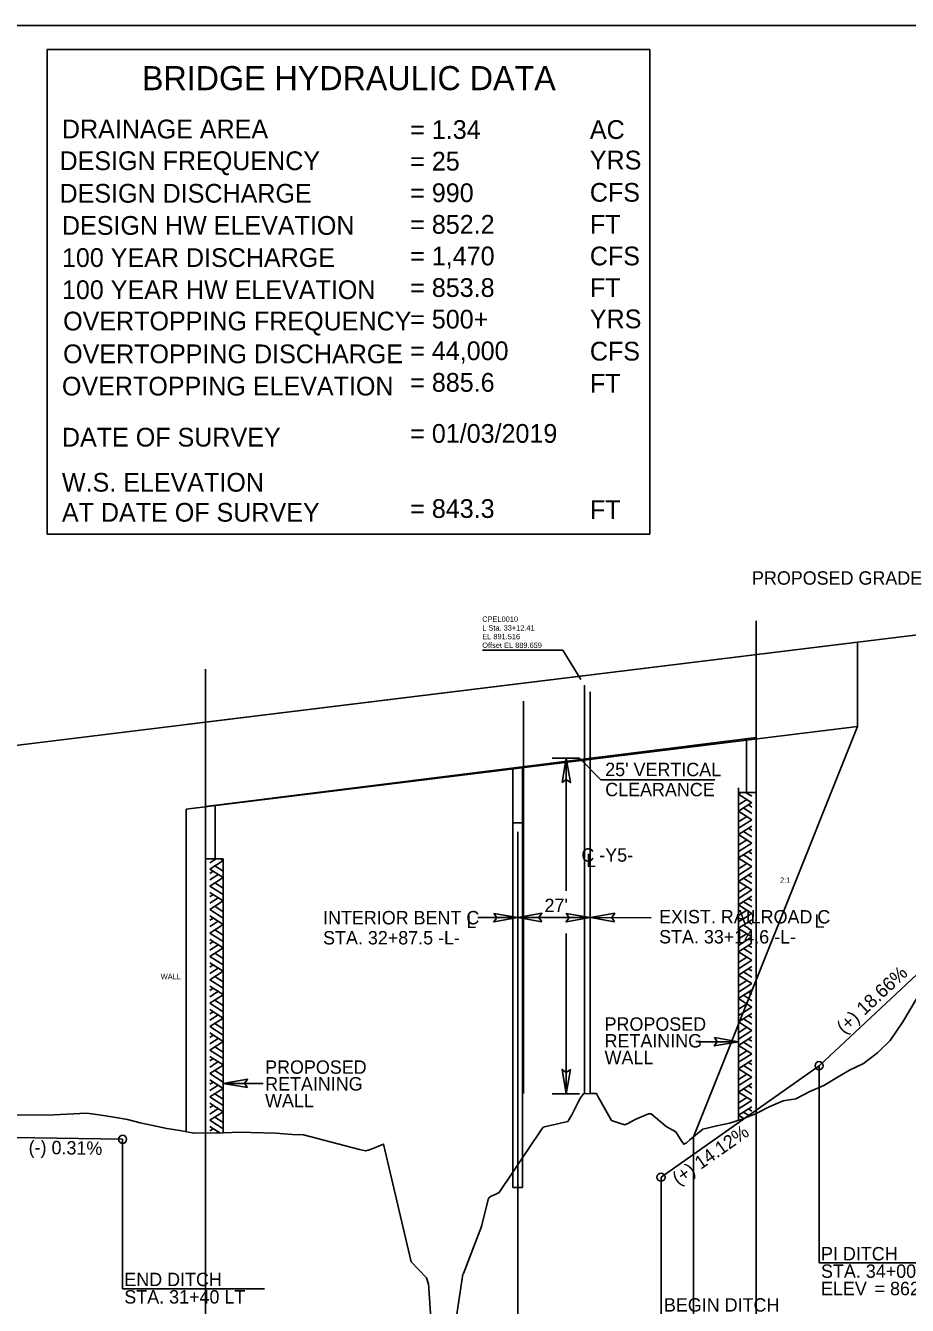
# Model space of a CAD drawing. Extents: x 1968019 to 1983409, y 545058 to 567558.
# Drawn here: x 1970946.7 to 1971275.9, y 566530.6 to 567008.4 of the extents above; entities that cross this region are included whole.
import ezdxf

# ---------------------------------------------------------------- set-up
doc = ezdxf.new("R2010")
doc.units = 0
for name, color, linetype in [('Exist Vertical Profile Ground Line', 7, 'Continuous'), ('Old_Level_20', 7, 'Continuous'), ('Prop Grid Mask', 7, 'Continuous'), ('Prop Plan Preparation Sheet Bridge Report Limited Study CELL', 7, 'Continuous'), ('Prop Roadway Bridge', 7, 'Continuous'), ('Prop Terminator CELL', 7, 'Continuous'), ('Prop Vertical Profile Ditch Grade Left', 7, 'Continuous'), ('Prop Vertical Profile Ditch Grade Left Label', 7, 'Continuous'), ('Prop Vertical Profile Grade', 7, 'Continuous'), ('Scratch_Level_1', 7, 'Continuous'), ('Scratch_Level_8', 7, 'Continuous'), ('Sheet Data Text CELL', 7, 'Continuous')]:
    doc.layers.add(name, color=color, linetype=linetype)

msp = doc.modelspace()

# ---------------------------------------------------------------- linework, layer by layer
at = {"layer": 'Exist Vertical Profile Ground Line'}
for points in [[(1971274.29, 566636.39), (1971279.33, 566645.04)], [(1971106.99, 566522.3), (1971109.93, 566542.19), (1971110.22, 566542.43), (1971116.96, 566559.99), (1971119.55, 566570.6), (1971120.52, 566571.34), (1971122.07, 566572.02), (1971123.55, 566572.68), (1971139.36, 566596.24), (1971140, 566597.16), (1971140.41, 566597.29), (1971149.23, 566599.25), (1971150.69, 566601.68), (1971153.07, 566606.51), (1971153.96, 566608.07), (1971154.97, 566609.62), (1971157.85, 566609.64), (1971159.91, 566609.65), (1971160.65, 566608.17), (1971161.6, 566606.49), (1971164.47, 566601.39), (1971165.48, 566599.66), (1971168.51, 566598.6), (1971170.44, 566598), (1971171.86, 566598.62), (1971174.29, 566599.95), (1971179.26, 566602.04), (1971180.33, 566602.12), (1971185.94, 566597.41), (1971189.54, 566595.36), (1971191.73, 566591.77), (1971192.28, 566591.09), (1971192.43, 566590.95), (1971192.45, 566590.71), (1971193.49, 566591.26), (1971194.72, 566592.36), (1971199.54, 566596.34), (1971204.8, 566597.64), (1971209.54, 566598.58), (1971214.29, 566600.07), (1971219.54, 566602.16), (1971224.29, 566604.77), (1971229.54, 566606.89), (1971234.29, 566607.73), (1971239.54, 566610.4), (1971244.8, 566612.64), (1971249.54, 566615.59), (1971254.29, 566618.36), (1971259.54, 566620.9), (1971264.8, 566624.91), (1971269.55, 566629.52), (1971274.29, 566636.39)], [(1970915.49, 566601.57), (1970957.3, 566601.67), (1970969.53, 566602.4), (1970974.27, 566601.74), (1970980.4, 566600.76), (1970984.79, 566599.95), (1970989.53, 566598.79), (1970994.28, 566597.71), (1970999.53, 566596.67), (1971004.28, 566595.84), (1971009.53, 566594.85), (1971020.55, 566595.01), (1971026.87, 566595.2), (1971030.89, 566595.08), (1971040.13, 566594.85), (1971046.38, 566594.41), (1971050.52, 566594.2), (1971071.37, 566588.81), (1971073.6, 566588.27), (1971074.15, 566588.41), (1971075.54, 566588.75), (1971080.41, 566590.8), (1971090.65, 566546.83), (1971096.42, 566540.87), (1971097.14, 566538.44), (1971097.26, 566537.05), (1971098.21, 566523.79)]]:
    msp.add_lwpolyline(points, dxfattribs=at)
at = {"layer": 'Prop Grid Mask'}
msp.add_lwpolyline([(1970954.74, 566999.5), (1971179.74, 566999.5), (1971179.74, 566818.58), (1970954.74, 566818.58)], close=True, dxfattribs=at)
at = {"layer": 'Prop Plan Preparation Sheet Bridge Report Limited Study CELL'}
for p, q in [((1971153.55, 566734.84), (1971143.38, 566734.84)), ((1971148.61, 566685.35), (1971148.61, 566734.84)), ((1971153.55, 566734.84), (1971161.5, 566726.82)), ((1971161.5, 566726.82), (1971204.04, 566726.82)), ((1971157.57, 566692.23), (1971157.57, 566609.63)), ((1971130.56, 566675.37), (1971115.61, 566675.37)), ((1971157.57, 566675.37), (1971130.46, 566675.37)), ((1971180.28, 566675.34), (1971157.67, 566675.4)), ((1971148.61, 566609.62), (1971148.61, 566669.37)), ((1971197.93, 566629.03), (1971212.87, 566629.03)), ((1971035.48, 566613.42), (1971020.54, 566613.42)), ((1971153.55, 566609.62), (1971143.38, 566609.62))]:
    msp.add_line(p, q, dxfattribs=at)
at = {"layer": 'Prop Roadway Bridge'}
for p, q in [((1971219.46, 566773.52), (1971219.46, 566742.57)), ((1971013.96, 566748.31), (1971013.96, 566716.88)), ((1971013.96, 566716.88), (1971219.46, 566742.57)), ((1971215.87, 566722.13), (1971215.87, 566742.13)), ((1971219.46, 566742.57), (1971219.46, 566722.13)), ((1971128.66, 566730.99), (1971128.66, 566710.73)), ((1971132.25, 566731.43), (1971132.25, 566710.73)), ((1971212.87, 566723.83), (1971212.87, 566631.65)), ((1971215.87, 566722.13), (1971212.87, 566722.13)), ((1971212.87, 566722.13), (1971212.87, 566599.63)), ((1971212.87, 566721.47), (1971213.9, 566722.13)), ((1971212.87, 566721.47), (1971217.87, 566718.28)), ((1971212.87, 566717.47), (1971216.01, 566719.47)), ((1971212.87, 566715.1), (1971217.87, 566718.29)), ((1971215.56, 566722.13), (1971217.87, 566720.66)), ((1971219.46, 566722.13), (1971215.87, 566722.13)), ((1971013.96, 566716.88), (1971013.96, 566697.33)), ((1971017.54, 566697.33), (1971017.54, 566717.33)), ((1971212.87, 566715.1), (1971217.87, 566711.93)), ((1971212.87, 566711.11), (1971216.01, 566713.11)), ((1971214.74, 566716.29), (1971217.87, 566714.29)), ((1971216.6, 566717.48), (1971217.87, 566716.66)), ((1971128.66, 566574.56), (1971128.66, 566710.73)), ((1971128.66, 566710.73), (1971132.25, 566710.73)), ((1971132.25, 566574.56), (1971132.25, 566710.73)), ((1971212.87, 566708.74), (1971217.87, 566711.93)), ((1971212.87, 566706.38), (1971217.87, 566709.55)), ((1971216.6, 566708.74), (1971217.87, 566707.93)), ((1971212.87, 566706.38), (1971217.87, 566703.19)), ((1971212.87, 566702.38), (1971216.01, 566704.38)), ((1971214.74, 566707.55), (1971217.87, 566705.56)), ((1971212.87, 566700.01), (1971217.87, 566703.19)), ((1971212.87, 566697.64), (1971217.87, 566700.81)), ((1971214.74, 566698.83), (1971216.6, 566697.64)), ((1971216.6, 566700.01), (1971217.87, 566699.2)), ((1971013.96, 566697.33), (1971017.54, 566697.33)), ((1971017.85, 566697.33), (1971015.54, 566695.85)), ((1971020.54, 566696.67), (1971015.54, 566693.49)), ((1971020.54, 566692.68), (1971017.4, 566694.68)), ((1971017.54, 566697.33), (1971020.54, 566697.33)), ((1971020.54, 566696.67), (1971019.5, 566697.33)), ((1971020.54, 566697.33), (1971020.54, 566595.01)), ((1971212.87, 566697.64), (1971212.95, 566697.59)), ((1971212.87, 566693.61), (1971216.01, 566695.6)), ((1971212.87, 566691.24), (1971217.87, 566694.41)), ((1971212.9, 566697.59), (1971217.87, 566694.41)), ((1971216.61, 566697.59), (1971217.87, 566696.79)), ((1971020.54, 566690.3), (1971015.54, 566693.49)), ((1971016.81, 566692.68), (1971015.54, 566691.86)), ((1971018.68, 566691.49), (1971015.54, 566689.49)), ((1971020.54, 566690.3), (1971015.54, 566687.13)), ((1971212.87, 566688.86), (1971217.87, 566692.05)), ((1971214.74, 566690.05), (1971217.87, 566688.05)), ((1971216.6, 566691.24), (1971217.87, 566690.43)), ((1971020.54, 566683.94), (1971015.54, 566687.13)), ((1971020.54, 566681.58), (1971015.54, 566684.75)), ((1971020.54, 566686.31), (1971017.4, 566688.31)), ((1971212.87, 566688.86), (1971217.87, 566685.69)), ((1971212.87, 566684.88), (1971216.01, 566686.88)), ((1971212.87, 566682.5), (1971217.87, 566685.69)), ((1971016.81, 566683.94), (1971015.54, 566683.13)), ((1971018.68, 566682.75), (1971015.54, 566680.76)), ((1971020.54, 566681.58), (1971015.54, 566678.39)), ((1971020.54, 566677.58), (1971017.4, 566679.58)), ((1971212.87, 566680.14), (1971217.87, 566683.31)), ((1971212.87, 566680.14), (1971217.87, 566676.95)), ((1971214.74, 566681.31), (1971217.87, 566679.33)), ((1971216.6, 566682.5), (1971217.87, 566681.69)), ((1971020.54, 566675.21), (1971015.54, 566678.39)), ((1971020.54, 566672.84), (1971015.54, 566676.01)), ((1971016.81, 566675.21), (1971015.54, 566674.4)), ((1971212.87, 566676.14), (1971216.01, 566678.14)), ((1971212.87, 566673.78), (1971217.87, 566676.95)), ((1971020.51, 566672.79), (1971015.54, 566669.61)), ((1971016.8, 566672.79), (1971015.54, 566671.99)), ((1971018.68, 566674.03), (1971016.81, 566672.84)), ((1971020.54, 566668.81), (1971017.4, 566670.8)), ((1971020.54, 566672.84), (1971020.46, 566672.79)), ((1971212.87, 566671.4), (1971217.87, 566674.58)), ((1971212.87, 566671.4), (1971212.95, 566671.35)), ((1971212.9, 566671.35), (1971217.87, 566668.18)), ((1971214.74, 566672.59), (1971216.6, 566671.4)), ((1971216.6, 566673.78), (1971217.87, 566672.96)), ((1971216.61, 566671.35), (1971217.87, 566670.55)), ((1971020.54, 566666.44), (1971015.54, 566669.61)), ((1971020.54, 566664.06), (1971015.54, 566667.25)), ((1971016.81, 566666.44), (1971015.54, 566665.63)), ((1971018.68, 566665.25), (1971015.54, 566663.25)), ((1971212.87, 566667.38), (1971216.01, 566669.36)), ((1971212.87, 566665), (1971217.87, 566668.18)), ((1971212.87, 566662.63), (1971217.87, 566665.81)), ((1971020.54, 566664.06), (1971015.54, 566660.89)), ((1971020.54, 566657.7), (1971015.54, 566660.89)), ((1971020.54, 566660.08), (1971017.4, 566662.08)), ((1971212.87, 566662.63), (1971217.87, 566659.45)), ((1971212.87, 566658.64), (1971216.01, 566660.64)), ((1971214.74, 566663.81), (1971217.87, 566661.81)), ((1971216.6, 566665), (1971217.87, 566664.19)), ((1971020.54, 566655.34), (1971015.54, 566658.51)), ((1971016.81, 566657.7), (1971015.54, 566656.89)), ((1971018.68, 566656.51), (1971015.54, 566654.53)), ((1971212.87, 566656.26), (1971217.87, 566659.45)), ((1971212.87, 566653.9), (1971217.87, 566657.08)), ((1971216.6, 566656.26), (1971217.87, 566655.45)), ((1971020.54, 566655.34), (1971015.54, 566652.15)), ((1971020.54, 566648.98), (1971015.54, 566652.15)), ((1971020.54, 566651.34), (1971017.4, 566653.34)), ((1971212.87, 566653.9), (1971217.87, 566650.71)), ((1971212.87, 566649.9), (1971216.01, 566651.9)), ((1971214.74, 566655.08), (1971217.87, 566653.09)), ((1971020.54, 566646.6), (1971015.54, 566649.78)), ((1971016.81, 566648.98), (1971015.54, 566648.16)), ((1971020.51, 566646.55), (1971015.54, 566643.38)), ((1971016.8, 566646.55), (1971015.54, 566645.75)), ((1971018.68, 566647.79), (1971016.81, 566646.6)), ((1971020.54, 566646.6), (1971020.46, 566646.55)), ((1971212.87, 566647.54), (1971217.87, 566650.71)), ((1971212.87, 566645.16), (1971217.87, 566648.34)), ((1971214.74, 566646.35), (1971216.6, 566645.16)), ((1971216.6, 566647.54), (1971217.87, 566646.73)), ((1971020.54, 566640.2), (1971015.54, 566643.38)), ((1971020.54, 566642.58), (1971017.4, 566644.56)), ((1971212.87, 566645.16), (1971212.95, 566645.11)), ((1971212.87, 566641.14), (1971216.01, 566643.13)), ((1971212.87, 566638.76), (1971217.87, 566641.94)), ((1971212.9, 566645.11), (1971217.87, 566641.94)), ((1971216.61, 566645.11), (1971217.87, 566644.31)), ((1971020.54, 566637.83), (1971015.54, 566641.01)), ((1971016.81, 566640.2), (1971015.54, 566639.39)), ((1971018.68, 566639.01), (1971015.54, 566637.01)), ((1971020.54, 566637.83), (1971015.54, 566634.65)), ((1971212.87, 566636.39), (1971217.87, 566639.58)), ((1971214.74, 566637.58), (1971217.87, 566635.58)), ((1971216.6, 566638.76), (1971217.87, 566637.95)), ((1971020.54, 566631.46), (1971015.54, 566634.65)), ((1971020.54, 566629.1), (1971015.54, 566632.28)), ((1971020.54, 566633.84), (1971017.4, 566635.84)), ((1971212.87, 566636.39), (1971217.87, 566633.21)), ((1971212.87, 566632.4), (1971216.01, 566634.4)), ((1971212.87, 566630.02), (1971217.87, 566633.19)), ((1971016.81, 566631.46), (1971015.54, 566630.65)), ((1971018.68, 566630.28), (1971015.54, 566628.29)), ((1971020.54, 566629.1), (1971015.54, 566625.91)), ((1971020.54, 566625.1), (1971017.4, 566627.1)), ((1971212.87, 566627.64), (1971217.87, 566630.83)), ((1971212.87, 566627.64), (1971217.87, 566624.47)), ((1971214.74, 566628.83), (1971217.87, 566626.83)), ((1971216.6, 566630.02), (1971217.87, 566629.2)), ((1971020.54, 566622.74), (1971015.54, 566625.91)), ((1971020.54, 566620.36), (1971015.54, 566623.54)), ((1971016.81, 566622.74), (1971015.54, 566621.93)), ((1971212.87, 566623.65), (1971216.01, 566625.65)), ((1971212.87, 566621.34), (1971217.87, 566624.52)), ((1971020.51, 566620.31), (1971015.54, 566617.14)), ((1971016.8, 566620.31), (1971015.54, 566619.51)), ((1971018.68, 566621.55), (1971016.81, 566620.36)), ((1971020.54, 566616.34), (1971017.4, 566618.33)), ((1971020.54, 566620.36), (1971020.46, 566620.31)), ((1971212.87, 566618.95), (1971217.87, 566622.14)), ((1971212.87, 566618.95), (1971217.87, 566615.77)), ((1971214.74, 566620.14), (1971217.87, 566618.14)), ((1971216.6, 566621.32), (1971217.87, 566620.51)), ((1971020.54, 566613.96), (1971015.54, 566617.14)), ((1971020.54, 566611.59), (1971015.54, 566614.78)), ((1971016.81, 566613.96), (1971015.54, 566613.15)), ((1971018.68, 566612.78), (1971015.54, 566610.78)), ((1971212.87, 566614.96), (1971216.01, 566616.96)), ((1971212.87, 566612.65), (1971217.87, 566615.82)), ((1971212.87, 566610.23), (1971217.87, 566613.42)), ((1971020.54, 566611.59), (1971015.54, 566608.41)), ((1971020.54, 566605.22), (1971015.54, 566608.39)), ((1971020.54, 566607.6), (1971017.4, 566609.6)), ((1971212.87, 566610.23), (1971217.87, 566607.05)), ((1971212.87, 566606.24), (1971216.01, 566608.24)), ((1971214.74, 566611.42), (1971217.87, 566609.42)), ((1971216.6, 566612.6), (1971217.87, 566611.79)), ((1971020.54, 566602.84), (1971015.54, 566606.03)), ((1971016.81, 566605.22), (1971015.54, 566604.4)), ((1971018.68, 566604.03), (1971015.54, 566602.03)), ((1971212.87, 566603.93), (1971217.87, 566607.1)), ((1971212.87, 566601.55), (1971217.87, 566604.74)), ((1971216.6, 566603.93), (1971217.87, 566603.12)), ((1971020.54, 566602.84), (1971015.54, 566599.67)), ((1971020.54, 566596.54), (1971015.54, 566599.72)), ((1971020.54, 566598.85), (1971017.4, 566600.85)), ((1971212.87, 566601.55), (1971214.85, 566600.3)), ((1971214.74, 566602.74), (1971217.14, 566601.21)), ((1971019.24, 566594.99), (1971015.54, 566597.35)), ((1971016.81, 566596.54), (1971015.54, 566595.73)), ((1971018.68, 566595.35), (1971018.09, 566594.98)), ((1971128.66, 566574.56), (1971128.66, 566574.56)), ((1971128.66, 566574.56), (1971132.25, 566574.56))]:
    msp.add_line(p, q, dxfattribs=at)
for points in [[(1971212.87, 566697.59), (1971212.87, 566671.4)], [(1971020.54, 566672.79), (1971020.54, 566646.6)], [(1971212.87, 566671.35), (1971212.87, 566645.16)], [(1971020.54, 566646.55), (1971020.54, 566620.36)], [(1971212.87, 566645.11), (1971212.87, 566631.65)], [(1971020.54, 566620.31), (1971020.54, 566606.85)]]:
    msp.add_lwpolyline(points, dxfattribs=at)
at = {"layer": 'Prop Terminator CELL'}
for points in [[(1971147.06, 566725.84), (1971148.61, 566734.84), (1971150.21, 566725.79), (1971148.61, 566726.94)], [(1971121.56, 566676.92), (1971130.56, 566675.37), (1971121.51, 566673.77), (1971122.66, 566675.37)], [(1971139.46, 566673.82), (1971130.46, 566675.37), (1971139.51, 566676.97), (1971138.36, 566675.37)], [(1971148.57, 566676.92), (1971157.57, 566675.37), (1971148.52, 566673.77), (1971149.67, 566675.37)], [(1971166.66, 566673.83), (1971157.67, 566675.4), (1971166.72, 566676.98), (1971165.57, 566675.38)], [(1971203.87, 566630.58), (1971212.87, 566629.03), (1971203.82, 566627.43), (1971204.97, 566629.03)], [(1971150.16, 566618.62), (1971148.61, 566609.62), (1971147.01, 566618.67), (1971148.61, 566617.52)], [(1971029.54, 566611.87), (1971020.54, 566613.42), (1971029.59, 566615.02), (1971028.44, 566613.42)]]:
    msp.add_lwpolyline(points, close=True, dxfattribs=at)
at = {"layer": 'Prop Vertical Profile Ditch Grade Left'}
for points in [[(1971183.96, 566578.43), (1971242.96, 566620.08), (1971292.96, 566666.73)], [(1970727.96, 566615.13), (1970842.96, 566594.73), (1970982.96, 566592.58)]]:
    msp.add_lwpolyline(points, dxfattribs=at)
at = {"layer": 'Prop Vertical Profile Ditch Grade Left Label'}
for p, q in [((1971242.96, 566620.08), (1971242.96, 566546.45)), ((1970982.96, 566536.81), (1970982.96, 566592.58)), ((1971183.96, 566578.43), (1971183.96, 566527.34)), ((1971297.23, 566546.45), (1971242.96, 566546.45)), ((1970982.96, 566536.81), (1971035.91, 566536.81))]:
    msp.add_line(p, q, dxfattribs=at)
for centre in [(1971242.96, 566620.08), (1970982.96, 566592.58), (1971183.96, 566578.43)]:
    msp.add_circle(centre, 1.5, dxfattribs=at)
at = {"layer": 'Prop Vertical Profile Grade'}
msp.add_line((1970942.96, 566739.6), (1971612.96, 566821.8), dxfattribs=at)
at = {"layer": 'Scratch_Level_1'}
for p, q in [((1971219.46, 566295.93), (1971219.46, 566786.18)), ((1971006.66, 566747.41), (1971257.34, 566778.17)), ((1971117.35, 566775.23), (1971147.34, 566775.23)), ((1971147.34, 566775.23), (1971154.03, 566764.28)), ((1971257.34, 566746.67), (1971257.34, 566778.17)), ((1971013.96, 566295.93), (1971013.96, 566768.12)), ((1971155.37, 566609.62), (1971155.37, 566762.1)), ((1971132.57, 566609.63), (1971132.57, 566756.13)), ((1971157.57, 566728.22), (1971157.57, 566759.72)), ((1971157.57, 566609.63), (1971157.57, 566756.13)), ((1971006.66, 566715.91), (1971257.34, 566746.67)), ((1971196.05, 566593.46), (1971257.34, 566746.67)), ((1971157.57, 566728.22), (1971157.57, 566609.63)), ((1971006.66, 566715.91), (1971006.66, 566595.39)), ((1971130.46, 566295.93), (1971130.46, 566707.38)), ((1971196.05, 566593.46), (1971196.05, 566514.57))]:
    msp.add_line(p, q, dxfattribs=at)
at = {"layer": 'Scratch_Level_8'}
msp.add_lwpolyline([(1970942.96, 566508.43), (1972342.96, 566508.43), (1972342.96, 567008.43), (1970942.96, 567008.43)], close=True, dxfattribs=at)
at = {"layer": 'Sheet Data Text CELL'}
msp.add_lwpolyline([(1970954.74, 566818.58), (1971179.74, 566818.58), (1971179.74, 566999.5), (1970954.74, 566999.5)], close=True, dxfattribs=at)

# ---------------------------------------------------------------- texts
at = {"layer": 'Old_Level_20'}
msp.add_text('PROPOSED GRADE', height=5, rotation=360, dxfattribs=at).set_placement((1971217.93, 566799.67))
at = {"layer": 'Prop Plan Preparation Sheet Bridge Report Limited Study CELL'}
for s, p in [("25' VERTICAL", (1971163.13, 566728.2)), ('CLEARANCE', (1971163.13, 566720.7)), ('C -Y5-', (1971154.22, 566696.26)), ('L', (1971155.99, 566694.23)), ('EXIST. RAILROAD C', (1971183.26, 566673.23)), ('L', (1971241.29, 566671.61)), ('STA. 33+14.6 -L-', (1971183.25, 566665.73))]:
    msp.add_text(s, height=5, rotation=359.9357, dxfattribs=at).set_placement(p)
for s, p in [("27'", (1971140.47, 566677.42)), ('INTERIOR BENT C', (1971057.8, 566672.84)), ('L', (1971111.3, 566671.46)), ('STA. 32+87.5 -L-', (1971057.8, 566665.34)), ('PROPOSED', (1971162.9, 566633.12)), ('RETAINING', (1971162.9, 566626.87)), ('WALL', (1971162.9, 566620.62)), ('PROPOSED', (1971036.16, 566617.05)), ('RETAINING', (1971036.16, 566610.8)), ('WALL', (1971036.16, 566604.55))]:
    msp.add_text(s, height=5, dxfattribs=at).set_placement(p)
at = {"layer": 'Prop Vertical Profile Ditch Grade Left Label'}
for s, rotation, p in [('(+) 18.66%', 43.0149, (1971252.38, 566631.65)), ('(+) 14.12%', 35.2195, (1971190.43, 566575.24)), ('(-) 0.31%', 359.1202, (1970947.86, 566587.15))]:
    msp.add_text(s, height=5, rotation=rotation, dxfattribs=at).set_placement(p)
for s, p in [('PI DITCH', (1971243.7, 566547.37)), ('STA. 34+00 LT', (1971243.7, 566540.87)), ('END DITCH', (1970983.61, 566537.76)), ('STA. 31+40 LT', (1970983.61, 566531.26)), ('ELEV', (1971243.7, 566534.37)), ('= 862.33', (1971263.7, 566534.37)), ('BEGIN DITCH', (1971185.06, 566528.26))]:
    msp.add_text(s, height=5, dxfattribs=at).set_placement(p)
at = {"layer": 'Scratch_Level_1'}
for s, p in [('CPEL0010', (1971117.23, 566785.8)), ('L Sta. 33+12.41', (1971117.23, 566782.55)), ('EL 891.516', (1971117.23, 566779.3)), ('Offset EL 889.659', (1971117.23, 566776.05)), ('2:1', (1971228.41, 566688.37)), ('WALL', (1970997.19, 566652.37))]:
    msp.add_text(s, height=2, dxfattribs=at).set_placement(p)
at = {"layer": 'Sheet Data Text CELL'}
for s, height, p in [('BRIDGE HYDRAULIC DATA', 8.9997, (1970990.19, 566984.31)), ('DRAINAGE AREA', 6.9999, (1970960.31, 566966.31)), ('= 1.34', 7, (1971090.34, 566966.11)), ('AC', 7, (1971157.4, 566966.11)), ('DESIGN FREQUENCY', 6.9999, (1970959.41, 566954.46)), ('YRS', 7, (1971157.4, 566954.71)), ('= 25', 7, (1971090.34, 566954.31)), ('DESIGN DISCHARGE', 6.9999, (1970959.41, 566942.31)), ('= 990', 7, (1971090.34, 566942.51)), ('CFS', 7, (1971157.4, 566942.66)), ('= 852.2', 7, (1971090.34, 566930.71)), ('FT', 7, (1971157.4, 566930.71)), ('DESIGN HW ELEVATION', 6.9999, (1970960.31, 566930.31)), ('100 YEAR DISCHARGE', 6.9999, (1970960.31, 566918.31)), ('= 1,470', 7, (1971090.34, 566918.91)), ('CFS', 7, (1971157.4, 566918.91)), ('= 853.8', 7, (1971090.34, 566907.11)), ('FT', 7, (1971157.4, 566907.11)), ('100 YEAR HW ELEVATION', 6.9999, (1970960.31, 566906.31)), ('OVERTOPPING FREQUENCY', 6.9999, (1970960.76, 566894.61)), ('= 500+', 7, (1971090.34, 566895.31)), ('YRS', 7, (1971157.4, 566895.41)), ('= 44,000', 7, (1971090.34, 566883.51)), ('CFS', 7, (1971157.4, 566883.36)), ('OVERTOPPING DISCHARGE', 6.9999, (1970960.76, 566882.36)), ('OVERTOPPING ELEVATION', 6.9999, (1970960.31, 566870.31)), ('= 885.6', 7, (1971090.34, 566871.71)), ('FT', 7, (1971157.4, 566871.31)), ('DATE OF SURVEY', 6.9999, (1970960.31, 566851.24)), ('= 01/03/2019', 6.9999, (1971090.34, 566852.64)), ('W.S. ELEVATION', 6.9999, (1970960.31, 566834.41)), ('AT DATE OF SURVEY', 6.9999, (1970960.31, 566823.2)), ('= 843.3', 7, (1971090.34, 566824.6)), ('FT', 7, (1971157.4, 566824.2))]:
    msp.add_text(s, height=height, rotation=360, dxfattribs=at).set_placement(p)

doc.saveas('drawing.dxf')
